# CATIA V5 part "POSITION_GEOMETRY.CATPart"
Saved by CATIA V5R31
Part number: POSITION
Bounding box of the stored display mesh (mm): x 0 to 0, y -17.588 to 17.588, z -24.418 to -4.184
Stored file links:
  \\solize.local\damia\dept\DDE_Design\10_order\2305701_JAMA_変換検証STEP3_お手本モデル作成\work\03_東洋電装_スイッチ\10_CATIA_V5\POSITION_GEOMETRY.CATPart
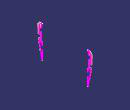
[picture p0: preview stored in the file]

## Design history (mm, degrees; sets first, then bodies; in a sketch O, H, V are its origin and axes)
AxisSystem1: origin (0, 0, 0), X (1, 0, 0), Y (0, 1, 0), Z (0, 0, 1)
Set1 "Position"
  Set2 "P1"
    DatumCurve1
    Symmetry1: ToTransfor DatumCurve1, Reference zx-plane
  Set3 "P2"
    DatumCurve2
    Symmetry2: ToTransfor DatumCurve2, Reference zx-plane
Body1 (main body)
